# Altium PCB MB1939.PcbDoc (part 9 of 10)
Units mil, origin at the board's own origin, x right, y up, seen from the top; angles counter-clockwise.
Board outline 5910.64 x 4335.93 mil, 6 copper layers (Top Layer, l2_GND, L3_SIG, L4_VCC, L5_GND, Bottom Layer), stack 58.424 mil thick; 635 components, 489 nets, 2289 pads, 1388 vias.
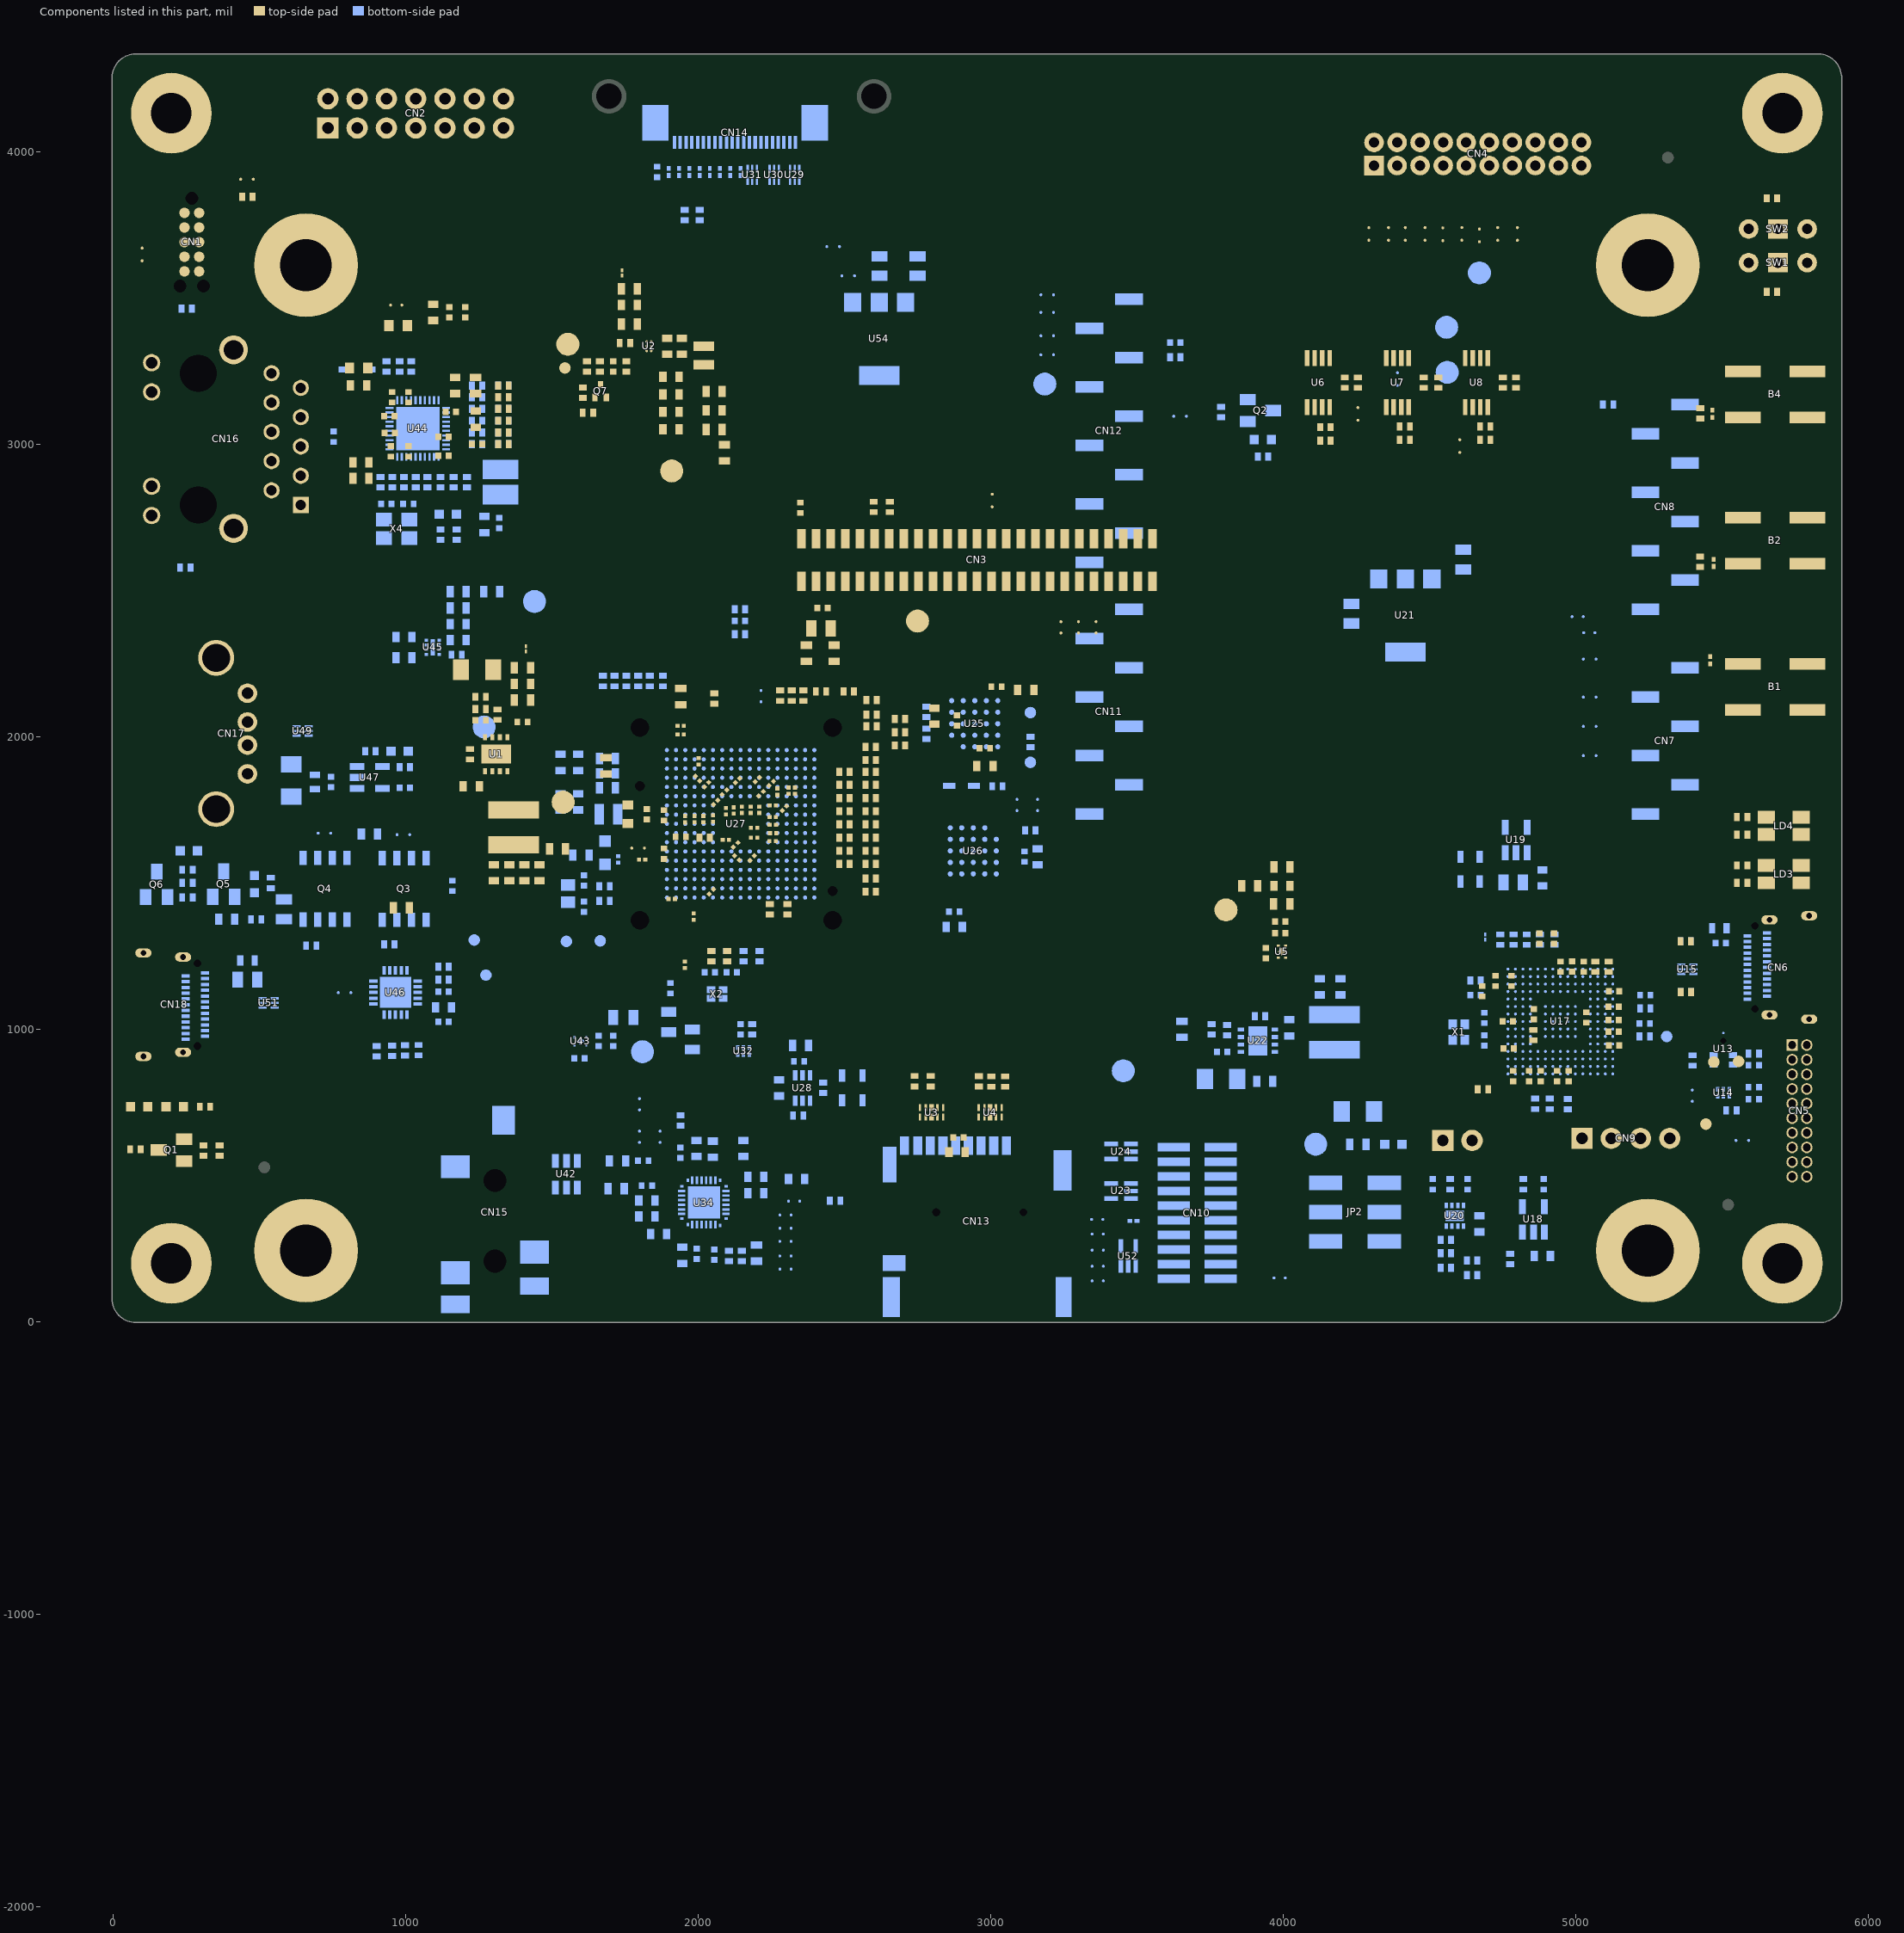
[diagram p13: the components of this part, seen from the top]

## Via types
v1: diameter 20, hole 10, Top Layer to Bottom Layer, tented both sides, 1072 vias
v2: diameter 16, hole 8, Top Layer to Bottom Layer, tented both sides, 316 vias

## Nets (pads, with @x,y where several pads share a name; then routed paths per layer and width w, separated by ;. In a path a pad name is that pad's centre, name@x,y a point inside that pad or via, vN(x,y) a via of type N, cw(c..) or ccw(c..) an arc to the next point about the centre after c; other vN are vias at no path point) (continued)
pads on no net: CN1.7 CN1.11 CN1.12 CN1.13 CN3.41 CN3.42 CN3.44 CN3.46 CN3.48 CN5.3 CN5.7 CN5.8 CN5.9 CN5.11 CN5.13 CN5.14 CN5.15 CN5.16 CN5.17 CN5.18 CN6.0 CN6.A2 CN6.A3 CN6.A8 CN6.A10 CN6.A11 CN6.B2 CN6.B3 CN6.B8 CN6.B10 CN6.B11 CN10.7 CN13.NPTH1 CN13.NPTH2 CN15.5 CN15.7 CN15.MT1 CN15.MT2 CN16.17 CN16.18 CN18.0 CN18.A2 CN18.A3 CN18.A8 CN18.A10 CN18.A11 CN18.B2 CN18.B3 CN18.B8 CN18.B10 CN18.B11 U3.4 U3.5 U3.6 U3.7 U13.6 U17.A1 U17.A2 U17.A3 U17.A4 U17.A5 U17.A8 U17.A9 U17.A11 U17.A12 U17.A13 U17.B1 U17.B2 U17.B3 U17.B4 U17.B5 U17.B6 U17.B7 U17.B8 U17.B9 U17.B10 U17.B11 U17.B12 U17.B13 U17.B14 U17.B15 U17.C2 U17.C3 U17.C12 U17.C13 U17.C14 U17.C15 U17.D1 U17.D2 U17.D3 U17.D11 U17.D13 U17.D14 U17.E1 U17.E2 U17.E3 U17.E4 U17.E12 U17.E13 U17.E14 U17.E15 U17.F1 U17.F4 U17.F14 U17.G4 U17.G14 U17.G15 U17.H2 U17.H3 U17.H4 U17.H14 U17.J3 U17.J4 U17.K1 U17.K2 U17.K3 U17.K12 U17.K13 U17.K14 U17.K15 U17.L1 U17.L12 U17.L13 U17.L14 U17.L15 U17.M2 U17.M3 U17.M4 U17.M7 U17.M12 U17.M13 U17.M14 U17.M15 U17.N2 U17.N4 U17.N6 U17.N7 U17.N11 U17.N13 U17.N14 U17.N15 U17.P2 U17.P4 U17.P5 U17.P6 U17.P7 U17.P8 U17.P9 U17.P10 U17.P11 U17.P12 U17.P13 U17.P14 U17.P15 U17.R2 U17.R3 U17.R6 U17.R7 U17.R8 U17.R9 U17.R10 U17.R11 U17.R12 U17.R13 U19.4 U25.A2 U25.A3 U25.B1 U25.B5 U27.NPTH1 U27.NPTH2 U27.NPTH3 U27.NPTH4 U27.NPTH5 U27.NPTH6 U28.4 U34.16 U34.17 U34.18 U34.25 U34.26

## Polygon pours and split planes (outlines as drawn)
GND on Top Layer "TOP-No Net" (solid, pour order 598): 17 vertices, not listed, extent 1736.9,2998.2 1972.9,3322.8
3V3_STLK on Top Layer "TOP-3V3_STLK" (solid, pour order 248): 62 vertices, not listed, extent 4720,100 5220,885
VDD1V8 on Top Layer "TOP-No Net" (solid, pour order 526): 1519,1692 1604,1692 1667,1629 1667,1571 1643,1547 1537,1547 1517,1567 1517,1639 1511,1645 1511,1679 1512,1680 1512,1685
VDDIO on Top Layer "TOP-VDDIO" (solid, pour order 190): 3844,1350 3699,1350 3680,1369 3680,1520 3700,1540 3855,1540 3869.98,1525.02 3869.98,1515.7 3838.82,1515.7 3838.82,1464.3 3869.98,1464.3 3869.98,1406.71 3870.01,1376.01
VDDCORE on Top Layer "TOP-VDDCORE 1" (solid, pour order 194): 2110,2965 2120,2955 2120,2915.04 2051.96,2847 1867,2847 1850,2864 1850,2950.98 1864.02,2965
VDDCORE on Top Layer "TOP-VDDCORE" (solid, pour order 196): 41 vertices, not listed, extent 1607.2,1915 1745,2091.8
VDD_HEXASPI_M on Top Layer "TOP-VDD_HEXASPI_M" (solid, pour order 198): 3235,1825 3245,1815 3245,1434 3112,1301 2925,1301 2910,1316 2910,1350 2919.49,1359.48 3034.53,1359.48 3035.04,1360 3042,1360 3135,1453 3135,1805 3155,1825 3235,1825
VDD_ETH on Top Layer "TOP-VDD_ETH" (solid, pour order 200): 166 vertices, not listed, extent 740,3225 960,3500
VDD3V3 on Top Layer "TOP-VDD3V3" (solid, pour order 202): 76 vertices, not listed, extent 975,3460 1040,3575
NetL3_1 on Top Layer "TOP-NETL3_1" (solid, pour order 208): 45 vertices, not listed, extent 1255,1715 1480,1860
NetC184_1 on Top Layer "TOP-NETC127_1" (solid, pour order 212): 864,1351 740,1475 740,1625 750,1635 1157,1635 1167,1625 1167,1510.47 1155.53,1499 999.58,1499 963,1462.42 963,1364 950,1351
NetC82_2 on Top Layer "TOP-NETC115_1" (solid, pour order 216): 21 vertices, not listed, extent 2430.02,2300 2515,2492.14
I_SENS_VDDIO_P on Top Layer "TOP-I_SENS_VDDIO_P" (solid, pour order 218): 29 vertices, not listed, extent 4000,1285 4075,1580
NetC21_2 on Top Layer "TOP-NETC50_2" (solid, pour order 222): 21 vertices, not listed, extent 1245,1540 1504,1665
NetC29_2 on Top Layer "TOP-NETC16_2" (solid, pour order 228): 39 vertices, not listed, extent 1725,1740 1896.79,1800
GND on Top Layer "TOP-GND 2" (solid, pour order 234): 50 vertices, not listed, extent 3900,1269.79 3979.98,1384.98
GND on Top Layer "TOP-GND 1" (solid, pour order 236): 1255,1420 1241.02,1433.98 1241.02,1516.02 1244.98,1519.98 1261.46,1519.98 1308.54,1519.98 1321.46,1519.98 1368.54,1519.98 1478.02,1519.98 1487,1511 1487,1429 1478,1420
GND on Top Layer "TOP-GND" (solid, pour order 238): 33 vertices, not listed, extent 1060,3460 1235,3552
5V on Top Layer "TOP-5V 3" (solid, pour order 240): 46 vertices, not listed, extent 1570,3370 1753.43,3550.5
5V on Top Layer "TOP-5V" (solid, pour order 246): 19 vertices, not listed, extent 1410,2085 1500,2255
3V3_DVDD_GMII on Top Layer "TOP-3V3_DVDD_GMII" (solid, pour order 250): 85 vertices, not listed, extent 995.37,3370 1265,3440
3V3_AVDD_GMII on Top Layer "TOP-3V3_AVDD_GMII" (solid, pour order 252): 81 vertices, not listed, extent 855,3165 1030,3290
1V05_AVDD_GMII on Top Layer "TOP-1V05_AVDD_GMII" (solid, pour order 254): 70 vertices, not listed, extent 854.91,2835 1045,3135
I_SENS_INT_VDDCORE_N on Top Layer "TOP-I_SENS_INT_VDDCORE_N" (solid, pour order 258): 1659.6,1815.4 1645,1830 1645,1890 1650,1895 1659.3,1895 1659.3,1853.82 1710.7,1853.82 1710.7,1895 1765,1895 1776.2,1883.8 1776.2,1833.9 1757.7,1815.4
I_SENS_VDDIO_N on Top Layer "TOP-I_SENS_VDDIO_N" (solid, pour order 260): 50 vertices, not listed, extent 3890,1405 3985,1600
NetC82_1 on Top Layer "TOP-NETC115_2" (solid, pour order 214): 26 vertices, not listed, extent 2280,2295 2410,2595
VBUS1 on Top Layer "TOP-VBUS1" (solid, pour order 206): 1027,1346 1002.01,1370.99 1002.01,1454.01 1026,1478 1129,1478 1143,1464 1143,1370 1119,1346
NetC137_2 on Top Layer "TOP-No Net" (solid, pour order 464): 4061,1007 3914,1007 3802,895 3802,763 3813,752 3900,752 3917,769 3917,892 3965,940 4056.31,940 4071,954.69 4071,1000
GND on Top Layer "TOP-No Net" (solid, pour order 470): 1219,2294 1208,2305 1140.25,2305 1130,2294.75 1130,2151 1139,2142 1206,2142 1219,2155
5V on Top Layer "TOP-No Net" (solid, pour order 466): 17 vertices, not listed, extent 3881,517 4338,1292
I_SENS_INT_N on Top Layer "TOP-No Net" (solid, pour order 468): 1265,2281 1356,2281 1386,2251 1386,2099 1395,2090 1395,1986 1387,1978 1347.89,1978 1342.55,1983.34 1342.55,2148.45 1311,2180 1261,2180 1254,2187 1254,2270
VDD_MIC on Top Layer "TOP-No Net" (solid, pour order 476): 5435,1019 5825,1019 5852,992 5852,475 5802,425 5630,425 5327,728 5327,918 5388,979
I_SENS_EXT_VDDCORE_P on Top Layer "TOP-No Net" (solid, pour order 588): 2060,3300 1990,3300 1955,3265 1925,3265 1918.6,3258.6 1918.6,3011.4 1934,2996 2021,2996 2040,3015 2040,3230 2050,3240 2060,3240 2074,3254 2074,3286
I_SENS_EXT_VDDCORE_N on Top Layer "TOP-No Net" (solid, pour order 586): 2068.81,3200 2145,3200 2160,3185 2160,2990 2145,2975 2065,2975 2055,2985 2055,3186.19
I_SENS_EXT_N on Top Layer "TOP-No Net" (solid, pour order 594): 1784.7,3570 1940,3570 1998.1,3511.9 1998.1,3371 1982,3354.9 1849.4,3354.9 1832.3,3354.9 1822.2,3365 1791,3365 1778.18,3377.82 1778.18,3563.48
VDDA1V8 on L3_SIG "TOP-No Net" (solid, pour order 488): 20 vertices, not listed, extent 1915,1760 2331,2228
5V_STLK on L3_SIG "L3_SIG-5V_STLK" (solid, pour order 280): 321 vertices, not listed, extent 4370,149.99 5000,515
5V_STLK on L3_SIG "L3_SIG-5V_STLK 1" (solid, pour order 278): 502 vertices, not listed, extent 4370,150 4980,515
VDDIO_SD on L3_SIG "TOP-No Net" (solid, pour order 500): 3044.4,987 3070,961.4 3070,855 3060,845 2270,845 2235.7,879.3 2075.7,879.3 2040,915 2040,955 2072,987
VBUS_STLK on L3_SIG "L3_SIG-VBUS_STLK" (solid, pour order 272): 29 vertices, not listed, extent 4645,365 4976,475
VBUS_STLK on L3_SIG "L3_SIG-VBUS_STLK 1" (solid, pour order 270): 32 vertices, not listed, extent 4645,390 4955,475
3V3_AVDD_GMII on L3_SIG "L3_SIG-3V3_AVDD_GMII" (solid, pour order 478): 960,3210 960,2920 950,2910 875,2910 865,2920 865,3205 880,3220 950,3220 960,3210
NetL7_2 on L3_SIG "TOP-No Net" (solid, pour order 498): 1794,1728 2094,1728 2108,1714 2108,1680 2104,1676 1808,1676 1784,1700 1784,1718
5V_USB_SNK on L3_SIG "TOP-No Net" (solid, pour order 264): 36 vertices, not listed, extent 817.7,25 4475,1720
VBUS1 on L3_SIG "L3_SIG-No Net" (solid, pour order 544): 295,910 515,910 525,920 545,940 545,1190 545,1395 535,1405 310,1405 275,1370 240,1335 240,950 280,910
VBUS_STLK on L3_SIG "L3_SIG-VBUS_STLK 3" (solid, pour order 266): 179 vertices, not listed, extent 5425,1120 5640,1415
3V3_STLK on L3_SIG "L3_SIG-No Net" (solid, pour order 558): 5241.98,876.98 5241.98,1501.98 5255,1515 5261.56,1515 5835,1515 5875,1555 5875,2065.83 5735,2205.83 4655.83,2205.83 4460,2010 4460,835 4490,805 5170,805
VDD1V8 on Bottom Layer "TOP-No Net" (solid, pour order 490): 17 vertices, not listed, extent 1512,1604.17 1804,1692
5V_STLK on Bottom Layer "TOP-No Net" (solid, pour order 584): 4605,190 4590,205 4590,325 4600,335 4642.44,335 4657.44,320 4754,320 4760,314 4760,250 4745.46,235.46 4650.46,235.46 4645,230 4645,195 4640,190
NetC126_2 on Bottom Layer "BOTTOM-NETC159_2" (solid, pour order 324): 4770,1630 4770,1535.58 4770,1468.44 4770,1460 4750,1440 4580,1440 4560,1460 4560,1530 4575,1545 4690,1545 4700,1555 4700,1630 4710,1640 4760,1640
GND on Bottom Layer "GND_L06_P556" (solid, remove dead copper, pour order 556): 4300,815 4360,815 4370,805 4370,660 4360,650 4290,650 4280,660 4280,795
VBUS_STLK on Bottom Layer "L3_SIG-No Net" (solid, pour order 554): 21 vertices, not listed, extent 5415,1260 5560,1420
VBUS1 on Bottom Layer "BOTTOM-VBUS1" (solid, pour order 314): 30 vertices, not listed, extent 378.2,1125 535.55,1345
VDDA1V8_AON on Bottom Layer "TOP-No Net" (solid, pour order 524): 19 vertices, not listed, extent 1755,856 1940,1108
VDDA1V8 on Bottom Layer "TOP-No Net" (solid, pour order 522): 1310,2538 1341,2538 1365,2514 1484,2514 1497,2501 1497,2402 1479,2384 1334,2384 1304,2414 1304,2531 1306,2533
5V_USB_SNK on Bottom Layer "TOP-No Net" (solid, pour order 502): 4273.75,418.75 4456.25,418.75 4475,400 4475,330 4465,320 4276.25,320 4265,331.25 4265,410
NetC184_1 on Bottom Layer "TOP-No Net" (solid, pour order 456): 810,1713 865,1713 874,1704 874,1436 857,1419 743,1419 731,1431 731,1621 740,1630 790,1630 796,1636 796,1698
GND on Bottom Layer "TOP-No Net" (solid, pour order 436): 4646.31,401.31 4773.69,401.31 4782,393 4782,347 4775,340 4650,340 4635,355 4635,390
I_SENS_VDDA1V8_N on Bottom Layer "BOTTOM-I_SENS_VDDA1V8_N" (solid, pour order 284): 28 vertices, not listed, extent 1192.91,2363.35 1290,2535
VDDIO_SD on Bottom Layer "BOTTOM-VDDIO_SD" (solid, pour order 288): 2040,955 2050,965 2110,965 2120,955 2120,920 2115,915 2055,915 2040,930 2040,955
VDDA1V8 on Bottom Layer "BOTTOM-VDDA1V8" (solid, pour order 292): 208 vertices, not listed, extent 3050,1700 3200,1760
VDD_OCTOSPI_M on Bottom Layer "BOTTOM-VDD_OCTOSPI_M" (solid, pour order 296): 81 vertices, not listed, extent 3060,1775 3125,1900
VDD_HEXASPI_M on Bottom Layer "BOTTOM-VDD_HEXASPI_M" (solid, pour order 302): 91 vertices, not listed, extent 3145.02,1770 3235,1825
VDD3V3 on Bottom Layer "BOTTOM-VDD3V3 1" (solid, pour order 304): 3430,880 3415,895 3415,970 3430,985 3664.3,985 3678,985 3690.55,972.45 3690.55,906.55 3664,880
VDD3V3 on Bottom Layer "BOTTOM-VDD3V3" (solid, pour order 306): 18 vertices, not listed, extent 1005,2305 1084.98,2445
VBUS_STLK on Bottom Layer "BOTTOM-VBUS_STLK" (solid, pour order 310): 4630,415 4600,415 4595,420 4595,460 4603,468 4612.96,468 4612.96,436.22 4647.04,436.22 4647.04,470 4727,470 4739,458 4739,421 4733,415
NetC171_2 on Bottom Layer "BOTTOM-NETC83_2" (solid, pour order 330): 20 vertices, not listed, extent 1615,970 1730,1105
NetC135_2 on Bottom Layer "BOTTOM-NETC54_2" (solid, pour order 334): 49 vertices, not listed, extent 3624,1010 4305,1135
I_SENS_INT_N on Bottom Layer "Bottom Layer-I_SENS_INT_N" (solid, pour order 336): 1255,1855 1255,1785 1250,1780 1220,1780 1215,1785 1215,1865 1355,2005 1355,2085 1365,2095 1390,2095 1395,2090 1395,1995 1255,1855
GND on Bottom Layer "BOTTOM-GND 17" (solid, pour order 338): 62 vertices, not listed, extent 1500,1370 1650,1565
GND on Bottom Layer "BOTTOM-GND 16" (solid, pour order 340): 29 vertices, not listed, extent 1495,1704 1626,1770
GND on Bottom Layer "BOTTOM-GND 15" (solid, pour order 342): 89 vertices, not listed, extent 845,2635 1080,2815.77
GND on Bottom Layer "BOTTOM-GND 14" (solid, pour order 344): 21 vertices, not listed, extent 1998.52,1065 2160,1175
GND on Bottom Layer "BOTTOM-GND 13" (solid, pour order 346): 35 vertices, not listed, extent 2060.55,1152.59 2103.98,1175
GND on Bottom Layer "BOTTOM-GND 12" (solid, pour order 348): 1489.68,1920.02 1479.5,1930.2 1479.5,1991.1 1488.4,2000 1591.6,2000 1615,1976.6 1615,1958.18 1566.98,1958.18 1566.98,1920.02 1554.04,1920.02 1554.04,1958.18 1506.98,1958.18 1506.98,1920.02 1489.68,1920.02
GND on Bottom Layer "BOTTOM-GND 9" (solid, pour order 354): 480,1130 475,1135 475,1145.72 506.36,1145.72 506.36,1192.78 475,1192.78 475,1201.28 475,1248.74 475,1265 480,1270 540,1270 550,1260 550,1145 535,1130
GND on Bottom Layer "BOTTOM-GND 7" (solid, pour order 358): 4824,114 4820.32,117.68 4820.32,209.69 4820,240 4845,265 4864.98,265 4864.98,251.71 4865.69,251 4864.67,248.54 4838.82,248.54 4838.82,201.46 4874.98,201.46 4874.98,151.71 4875.07,118.07 4871,114
GND on Bottom Layer "BOTTOM-GND 5" (solid, pour order 362): 18 vertices, not listed, extent 4075,1160 4270,1285
GND on Bottom Layer "BOTTOM-GND 4" (solid, pour order 364): 21 vertices, not listed, extent 4520,905 4702.9,1075
GND on Bottom Layer "BOTTOM-GND 2" (solid, pour order 368): 46 vertices, not listed, extent 4800,1415 4965,1516.16
GND on Bottom Layer "BOTTOM-GND 1" (solid, pour order 370): 32 vertices, not listed, extent 4122.5,2435 4675,2760
GND on Bottom Layer "BOTTOM-GND" (solid, pour order 372): 24 vertices, not listed, extent 1605.02,865 1740,950.85
5V on Bottom Layer "BOTTOM-5V" (solid, pour order 378): 45 vertices, not listed, extent 1500,870 1585,995
5V_STLK on Bottom Layer "BOTTOM-5V_STLK 1" (solid, pour order 382): 20 vertices, not listed, extent 4885,150 5000,350
3V3_STLK on Bottom Layer "BOTTOM-3V3_STLK 1" (solid, pour order 386): 41 vertices, not listed, extent 4735.6,123.2 4800.3,208
3V3_STLK on Bottom Layer "BOTTOM-3V3_STLK" (solid, pour order 388): 42 vertices, not listed, extent 4823.56,1535 4960,1630
1V05_GMII on Bottom Layer "BOTTOM-1V05_GMII" (solid, pour order 390): 23 vertices, not listed, extent 1215,2735 1410,2860
I_SENS_INT_VDDCORE_N on Bottom Layer "BOTTOM-I_SENS_INT_VDDCORE_N" (solid, pour order 392): 1736.18,1800 1736.18,1938.98 1740.79,1938.98 1763.29,1916.48 1774,1916.48 1774,1809 1765,1800
VIN on Bottom Layer "BOTTOM-VIN" (solid, pour order 286): 18 vertices, not listed, extent 4480,2365 5305,2605
UCPD_SNK on Bottom Layer "BOTTOM-UCPD_SNK" (solid, pour order 318): 905,1420 890.02,1434.98 890,1690 900,1700 975,1700 980,1695 980,1615.42 952.2,1615.42 952.2,1554.18 990,1554.18 990,1430 980,1420
NetL6_1 on Bottom Layer "BOTTOM-NETL4_1" (solid, pour order 320): 59 vertices, not listed, extent 4005,860 4300,970
5V_VIN on Bottom Layer "BOTTOM-5V_VIN" (solid, pour order 380): 22 vertices, not listed, extent 4130,2200 4530,2600
I_SENS_VDDA1V8_P on Bottom Layer "TOP-No Net" (solid, pour order 438): 1165,2517.64 1122.64,2517.64 1109.29,2504.29 1109.29,2308.14 1112.12,2305.32 1165,2305.32
GND on Bottom Layer "TOP-No Net" (solid, pour order 440): 1195,2351.65 1302.35,2351.65 1317,2337 1317,2260 1302,2245 1195,2245 1185,2255 1185,2303.35 1190,2308.35 1190,2349.68
GND on Bottom Layer "BOTTOM-GND 10" (solid, pour order 352): 41 vertices, not listed, extent 905,2305 980,2445
UCPD_SOURCE1 on Bottom Layer "TOP-No Net" (solid, pour order 442): 705,1715 610,1715 565,1670 565,1470 555,1460 545,1450 545,1425 554.09,1415.91 620.91,1415.91 635,1430 712.41,1430 717.13,1434.72 717.13,1702.87
GND on Bottom Layer "TOP-No Net" (solid, pour order 444): 570,1960 780,1960 795,1945 795,1860 790,1855 716.65,1855 711.65,1850 670,1850 654.25,1865.75 554.25,1865.75 545,1875 545,1935.63 549.37,1940
NetC137_2 on Bottom Layer "TOP-No Net" (solid, pour order 460): 3797,898 3837,898 3852,883 3905,883 3919,869 3919,763 3904,748 3808,748 3797,759 3797,859
5V on Bottom Layer "TOP-No Net" (solid, pour order 462): 3950,880 3992,880 4035,837 4187,837 4245,779 4245,218 4215,188 3971,188 3945,214 3945,871 3944,872
I_SENS_INT_VDDCORE_P on Bottom Layer "TOP-No Net" (solid, pour order 492): 17 vertices, not listed, extent 1466,1686 1680,1947.64
5V_STLK on Bottom Layer "TOP-No Net" (solid, pour order 510): 4289,550 4461,550 4471,540 4471,440 4465,434 4283,434 4274,443 4274,534 4275,535
VBUS_STLK on Bottom Layer "TOP-No Net" (solid, pour order 514): 4870.33,469 4987,469 4996,460 4996,380 4982,366 4873,366 4860,379 4860,459.46
GND on Bottom Layer "TOP-No Net" (solid, pour order 516): 4612,563 4598,549 4598,490 4606,482 4728,482 4738,492 4738,556 4731,563
GND on Bottom Layer "TOP-No Net" (solid, pour order 518): 4872,563 4855,546 4855,491 4867,479 4985,479 4998,492 4998,556 4991,563
VBUS2 on Bottom Layer "BOTTOM-VBUS2" (solid, pour order 312): 32 vertices, not listed, extent 400,1735 860,1925
GND on Bottom Layer "TOP-No Net" (solid, pour order 458): 3760,767 3644,767 3630,781 3630,856 3639,865 3676,865 3705,894 3705,938 3710,943 3779,943 3788,934 3788,888 3771.25,871.25 3771.25,777.25 3768,774
NetC200_2 on Bottom Layer "Top Layer-No Net" (solid, remove dead copper, pour order 536): 25 vertices, not listed, extent 2510,3150 2725,3603.54
5V on Bottom Layer "Top Layer-No Net" (solid, remove dead copper, pour order 538): 22 vertices, not listed, extent 2680,3400 2930,3695
GND on Bottom Layer "Top Layer-No Net" (solid, remove dead copper, pour order 540): 17 vertices, not listed, extent 2420,3365 2560,3545
GND on Bottom Layer "Top Layer-No Net" (solid, remove dead copper, pour order 542): 2565,3625 2795,3625 2800,3625 2810,3635 2815,3640 2815,3660 2815,3730 2805,3740 2575,3740 2555,3720 2555,3630 2560,3625
VDD_CAM on Bottom Layer "Bottom Layer-VDD_CAM" (solid, pour order 564): 2444,3553 2448,3549 2497,3549 2501.22,3553.22 2501.22,3596.22 2507,3602 2527,3602 2534,3609 2534,3717 2521,3730 2484,3730 2473.36,3719.36 2473.36,3657.36 2444,3628
NetL7_2 on Bottom Layer "TOP-No Net" (solid, pour order 496): 17 vertices, not listed, extent 1698,1675 1899,1787
NetC184_1 on Bottom Layer "BOTTOM-NETC127_1 1" (solid, pour order 326): 19 vertices, not listed, extent 1010.02,1425 1190,1635
VDDA1V8 on L4_VCC "L4_VCC-VDDA1V8" (solid, pour order 446): 1077 vertices, not listed, extent 1340,1355 4630,3620
5V on L4_VCC "L3_SIG-No Net" (solid, pour order 560): 1360,1390 1360,1520 1260,1520 1250,1510 1245,1505 1245,1415 1290,1415 1315,1390 1330,1390
5V on L4_VCC "TOP-No Net" (solid, pour order 482): 4160,4120 4733.45,4120 4810,4043.45 4810,3833.05 4786.95,3810 4190,3810 4140,3860
5V on L4_VCC "L4_VCC-5V" (solid, pour order 432): 3445 vertices, not listed, extent 610,825 5305,4120
VDDA18AON on L4_VCC "L4_SIG-NetR148_2" (solid, pour order 550): 25 vertices, not listed, extent 1750,1085 2105,1611.04
VBUS_STLK on L4_VCC "TOP-No Net" (solid, pour order 400): 5885.48,1474.98 5309.15,1474.98 5275.02,1440.85 5275.02,1204.02 4625.02,554.02 4625.02,359.12 4649.14,335 4820,335 5461,976 5884.48,976 5885.48,975
VDDIO_SD on L4_VCC "L4_VCC-VDDIO_SD" (solid, pour order 410): 316 vertices, not listed, extent 1895,825 2197.5,1607.5
VDD_OCTOSPI_M on L4_VCC "L4_VCC-VDD_OCTOSPI_M" (solid, pour order 424): 253 vertices, not listed, extent 2650,1790 3150,2220
VBUS_STLK on L4_VCC "TOP-No Net" (solid, pour order 398): 4804,333 4944,333 5033,422 5033,569 4753.17,569 4625.02,440.85 4625.02,359.12 4649.14,335
3V3_DVDD_GMII on L4_VCC "TOP-No Net" (solid, pour order 450): 1400,3360.86 1330.86,3430 1079.14,3430 884.14,3235 575.44,3235 555,3214.56 555,2695.86 474.14,2615 309.14,2615 295,2600.86 295,2564.14 344.14,2515 1010,2515 1010,2588 1400,2978
VDD3V3 on L4_VCC "TOP-No Net" (solid, pour order 480): 4835,4105 5039.69,4105 5063.98,4080.71 5063.98,3843.98 5050,3830 4850,3830 4830,3850
VBUS1 on L4_VCC "L3_SIG-No Net" (solid, pour order 562): 604.14,1485 1100.86,1485 1135,1450.86 1135,1109.14 1110.86,1085 1025,1085 994.14,1085 939.14,1140 875,1140 464.14,1140 445,1159.14 445,1325.86 604.14,1485
VDDCORE on L4_VCC "L4_VCC-VDDCORE" (solid, pour order 448): 850 vertices, not listed, extent 1635.6,1695.5 2352.5,2980
VDDIO on L4_VCC "L4_VCC-VDDIO" (solid, pour order 402): 2111 vertices, not listed, extent 1822.5,270 5885.48,4310.67
VDDIO on L4_VCC "TOP-No Net" (solid, pour order 520): 1848.9,1678.6 1705.6,1678.6 1693,1666 1693,1578 1714,1557 1754.78,1557 1815.3,1617.52 1849.12,1617.52
VDDA1V8_AON on L4_VCC "L4_SIG-VDDA1V8_AON" (solid, pour order 552): 26 vertices, not listed, extent 1615,825 1885,1605
VDD3V3 on L4_VCC "TOP-No Net" (solid, pour order 484): 65 vertices, not listed, extent 20.04,20.04 5885.48,4310.67
GND on l2_GND "L2_GND-GND 9" (solid, pour order 154): 20.04,20.04 20.04,4310.67 5885.48,4310.67 5885.48,20.04 20.04,20.04
GND on L5_GND "L5_GND-GND" (solid, pour order 396): 20.04,4310.67 5885.48,4310.67 5885.48,20.04 20.04,20.04 20.04,4310.67

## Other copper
Top Layer:
  text "1" at 2716.83,4267.41 h31.5
  text ".Layer_Name" at 1632.47,-1647.68 h118.11
  text ".GTL" at 3274,-1647.68 h118.11
l2_GND:
  pour cut-out: 20.5,75.1 75.8,19.8 19.6,19.8 19.6,75.18
  pour cut-out: 5830.5,20.6 5885.8,75.9 5885.8,19.7 5830.42,19.7
  pour cut-out: 5884.9,4255.98 5829.6,4311.28 5885.8,4311.28 5885.8,4255.9
  pour cut-out: 74.92,4310.2 19.62,4254.9 19.62,4311.1 75,4311.1
  text "2" at 2742.03,4267.41 h31.5
  text ".Layer_Name" at 1717.28,-1663.7 h118.11
  text ".G1" at 3311.28,-1671.7 h118.11
L3_SIG:
  text "3" at 2778.45,4267.41 h31.5
  text ".Layer_Name" at 1693.28,-1638.7 h118.11
  text ".G2" at 3307.28,-1658.7 h118.11
L4_VCC:
  pour cut-out: 76.3,4310.8 20.1,4254.6 20.1,4310.8
  pour cut-out: 20.04,76.24 76.24,20.04 20.04,20.04
  pour cut-out: 5829.4,19.9 5885.6,76.1 5885.6,19.9
  pour cut-out: 5885.6,4254.7 5829.4,4310.9 5885.6,4310.9
  text "4" at 2813.92,4267.41 h31.5
  text ".Layer_Name" at 1686.28,-1632.7 h118.11
  text ".G3" at 3296.28,-1645.7 h118.11
L5_GND:
  pour cut-out: 76.24,4310.67 20.04,4254.47 20.04,4310.67
  pour cut-out: 20.04,76.24 76.24,20.04 20.04,20.04
  pour cut-out: 5829.28,20.04 5885.48,76.24 5885.48,20.04
  pour cut-out: 5885.48,4254.47 5829.28,4310.67 5885.48,4310.67
  text "5" at 2847.7,4267.41 h31.5
  text ".Layer_Name" at 1686.28,-1640.7 h118.11
  text ".G4" at 3308.28,-1653.7 h118.11
Bottom Layer:
  text "6" at 2905.57,4267.41 h31.5
  text ".GBL" at 2832.93,-1648.93 h118.11
  text ".Layer_Name" at 4459.46,-1648.93 h118.11
Multi-Layer:
  pour cut-out: 2704,4321.74 2704,4243 2920.54,4243 2920.54,4321.74

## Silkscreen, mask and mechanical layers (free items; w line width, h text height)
Top Overlay:
  lines w5: 2010,1745 2065,1745 2065,1685 2005,1685 ; 2015,1745 2005,1745 2005,1685 ; 2080,1770 2080,1715 2225,1715 2225,1770 ; 2085,1775 2210,1775 ; 2115,1775 2115,1805 2192,1882 2192,1922 2215,1945 2215,1975 ; 2205,1965 2215,1975 ; 2225,1965 2215,1975 ; 3858,1294 3670,1294 3670,1234 3859,1234 3859,1294 ; 1960,1585 1960,1590 1960,1635 1980,1635 1980,1685 2005,1685 ; 1960,1585 2000,1585 2000,1490 1910,1490 1910,1585 1960,1585 ; 10,785 10,851.42 155,851.42 155,785 10,785 ; 170,785 315,785 315,851.42 170,851.42 170,785 ; 210,3365 210,3431.42 340,3431.42 340,3365 210,3365 ; 1315,3399 1565,3399 1565,3467 1315,3467 1315,3399 ; 1387,1844 1610,1844 1610,1904 1387,1904 1387,1844 ; 1792,2735 1792,2795 2075,2795 2075,2735 1792,2735 ; 2090,1975 2090,2085 2230,2085 2308.6,2085 2308.6,1975 2306.5,1975 2090,1975 ; 3425,2805 3545,2805 3545,2844.72 3545,2853.68 3545,2865 3425,2865 3425,2805 ; 5100,4075 5340,4075 5340,4141.42 5273.58,4141.42 5100,4141.42 5100,4075 ; 5605,1970 5775,1970 5775,2009.72 5775,2018.68 5775,2035 5605,2035 5605,1970 ; 5605,2455 5794.03,2455 5794.03,2520 5605,2520 5605,2455 ; 5625,2955 5794.03,2955 5794.03,3020 5625,3020 5625,2955 ; 5685,3425 5885,3425 5885,3441.6 5885,3474.81 5885,3491.42 5818.58,3491.42 5685,3491.42 5685,3425 ; 5685,3876.79 5685,3943.21 5818.58,3943.21 5885,3943.21 5885,3926.6 5885,3893.4 5885,3876.79 5685,3876.79 ; 5835,615 5895,615 5895,735 5855.28,735 5846.32,735 5835,735 5835,615
  text "N" at 1405,4180 h60
  text "STMOD+" at 5110,4090 h60
  text "P" at 1410,4050 h60
  text "GND" at 1050,3895 h60 r90
  text "BOOT0" at 5700,3891.79 h60
  text "INT_IN" at 955,3850 h60 r90
  text "VDDIO" at 1240,3850 h60 r90
  text "EXT_IN" at 740,3835 h60 r90
  text "L" at 5503.1,3793 h60
  text "H" at 5844.7,3790.1 h60
  text "VDDA1V8" at 1345,3775 h60 r90
  text "INT VCORE" at 1150,3725 h60 r90
  text "EXT VCORE" at 870,3715 h60 r90
  text "L" at 5503.9,3525.6 h60
  text "H" at 5845.5,3522.7 h60
  text "BOOT1" at 5700,3440 h60
  text "PWR_ON" at 1325,3417 h60
  text "TAG" at 220,3380 h60
  text "TAMP" at 5635,2965 h60
  text "LCD" at 3435,2815 h60
  text "VDDCORE" at 1802,2745 h60
  text "USER1" at 5615,2470 h60
  text "MCO1" at 2817,2320 h60
  text "NRST" at 5615,1985 h60
  text "VDD1V8" at 1394,1854 h60
  text "J" at 325,1830 h700 r90
  text "VDDIO" at 3681,1244 h60
  text "LED1" at 20,800 h60
  text "LED2" at 180,800 h60
  text "MIC" at 5885,625 h60 r90
  text ".Layer_Name" at 1632.47,-1647.68 h118.11
  text ".GTO" at 3274,-1647.68 h118.11
Bottom Overlay:
  lines w5: 2050,4234.66 2050,4260 2050,4285 ; 2050,4235 2300,4235 ; 2050,4285.34 2300,4285.34 ; 2300,4234.83 2300,4247.41 2300,4272.59 2300,4285.17 ; 2370,420 2385,420 2405,440 ; 2390,440 2405,440 ; 2405,425 2405,440 ; 3400,275 3310,275 3310,185 3310,155 3310,-5 3530,-5 3530,270 ; 4633.3,374.7 4639,380.4 4639,353.7 4642.35,350.35 ; 10,1640 300,1640 300,1703.75 10,1703.75 10,1640 ; 270,805 420,805 420,860 270,860 270,848.75 270,816.25 270,805 ; 280,2348.75 435,2348.75 435,2403.75 280,2403.75 280,2392.5 280,2360 280,2348.75 ; 445,2495 445,2560 750,2560 750,2495 595,2495 445,2495 ; 1015,230 1080,230 1080,580 1015,580 1015,385 1015,230 ; 1045,1905 1045,1927.5 1045,1960 1045,1968.75 1395,1968.75 1395,1905 1045,1905 ; 1051,2118 1334,2118 1334,2181.75 1051,2181.75 1051,2173 1051,2140.5 1051,2118 ; 1070,990 1070,1250 1190,1250 1190,1195 1190,1125 1350,1125 1350,875 1200,875 1200,990 1070,990 ; 1437,2520 1437,2538.5 1437,2571 1437,2579.75 1710,2579.75 1710,2520 1437,2520 ; 1859.7,837.6 1859.7,894.8 2022,894.8 2022,837.6 1909.6,837.6 1859.7,837.6 ; 2480,115 2480,370 2491.25,370 2523.75,370 2540,370 2540,115 2480,115 ; 3298,966 3298,983.25 3298,1021 3527,1021 3527,966 3387,966 3298,966 ; 3630,660 3685,660 3825,660 3825,715 3630,715 3630,660 ; 5500,1510 5720,1510 5875,1510 5875,1575 5500,1575 5500,1510
  lines w6: 310,1545 300,1555 ; 310,1565 300,1555 ; 340,1620 340,1555 300,1555
  text "CAMERA" at 2285,4240 h60
  text "MB1939C" at 5025,4155 h120
  text "E" at 1335,3642 h551.18
  text "K" at 1760,3620 h551.18
  text "I" at 3870,3535 h551.18
  text "MCO2" at 4590,3485 h60
  text "D15" at 3345,3480 h60
  text "D14" at 3345,3425 h60
  text "CSLEEP" at 4815,3325 h60
  text "C" at 2345,3250 h551.18
  text "CSTOP" at 4810,3170 h60
  text "PPS_OUT" at 3130,3135 h60
  text "D13" at 3265,3080 h60
  text "IOREF" at 5575,3000 h60
  text "D12" at 3270,2970 h60
  text "H" at 2870,2955 h551.18
  text "NRST" at 5580,2900 h60
  text "D11" at 3270,2880 h60
  text "S" at 2290,2865 h450
  text "3V3" at 5575,2805 h60
  text "D10" at 3270,2775 h60
  text "5V" at 5570,2705 h60
  text "D9" at 3270,2685 h60
  text "GND" at 5575,2595 h60
  text "D8" at 3270,2565 h60
  text "F" at 2885,2540 h551.18
  text "VDDA1V8" at 1693,2531 h60
  text "G" at 2400,2515 h551.18
  text "ETHERNET" at 740,2510 h60
  text "GND" at 5575,2510 h60
  text "VIN" at 5565,2415 h60
  text "D7" at 3270,2395 h60
  text "USB2" at 425,2360 h60
  text "D6" at 3270,2320 h60
  text "A0" at 5510,2215 h60
  text "D5" at 3270,2210 h60
  text "PWR_ON2" at 1317,2133 h60
  text "D4" at 3275,2120 h60
  text "A1" at 5510,2105 h60
  text "D3" at 3275,2020 h60
  text "A2" at 5515,2015 h60
  text "D2" at 3275,1950 h60
  text "USB2_FAULT" at 1385,1920 h60
  text "A3" at 5515,1910 h60
  text "D1" at 3270,1830 h60
  text "A4" at 5515,1810 h60
  text "D0" at 3335,1765 h60
  text "A5" at 5515,1715 h60
  text "USB1_OCP" at 295,1655 h60
  text "STLINK_V3EC" at 5865,1525 h60
  text "VDD3V3" at 3515,976 h60
  text "VAON" at 2015.8,848.5 h60
  text "USB1" at 410,815 h60
  text "MIPI20" at 3810,670 h60
  text "AUDIO JACK" at 1030,245 h60 r270
  text "1-2:5V_STLK" at 4370,150 h60
  text "SD-CARD" at 2490,125 h60 r270
  text "3-4:5V_USB_SNK" at 4370,90 h60
  text "5-6:5V_VIN" at 4365,25 h60
  text ".GBO" at 2832.93,-1648.93 h118.11
  text ".Layer_Name" at 4459.46,-1648.93 h118.11
Top Paste:
  text ".Layer_Name" at 1632.47,-1647.68 h118.11
  text ".GTP" at 3274,-1647.68 h118.11
Bottom Paste:
  text ".GBP" at 2832.93,-1648.93 h118.11
  text ".Layer_Name" at 4459.46,-1648.93 h118.11
Top Solder:
  text ".Layer_Name" at 1632.47,-1647.68 h118.11
  text ".GTS" at 3274,-1647.68 h118.11
Bottom Solder:
  text ".GBS" at 2832.93,-1648.93 h118.11
  text ".Layer_Name" at 4459.46,-1648.93 h118.11
M1-Board Shape:
  lines w5: -0.1,79.04 ccw(c78.64,79.04) 78.64,0.3 ; 0,72 0,4253.8 ; -0.01,4251.7 cw(c78.73,4251.97) 78.73,4330.71 ; 76.91,4330.71 5826.8,4330.71 ; 78.64,0 5833.81,0 ccw(c5833.81,71.52) 5905.33,71.52 ; 5826.51,4330.64 cw(c5826.77,4251.9) 5905.51,4251.9 5905.51,69.7
M2-Board Dimensions:
  text ".Layer_Name" at 1632.47,-1647.68 h118.11
  text ".GM2" at 3274,-1647.68 h118.11
M14-Top Assembly:
  text ".Layer_Name" at 1632.47,-1647.68 h118.11
  text ".GM14" at 3274,-1647.68 h118.11
M15-Bottom Assembly:
  text ".GM15" at 2832.93,-1648.93 h118.11
  text ".Layer_Name" at 4459.46,-1648.93 h118.11
Drill Drawing:
  drawing of 1182 lines, arcs and shapes, not listed
  text "4" at 6780.7,8171.7 h75
  text "4" at 6780.7,8171.7 h75
  text "LAYER STUCK-UP" at 6980.7,8171.7 h75
  text "LAYER STUCK-UP" at 6980.7,8171.7 h75
  text "SOLDERMASK & SILKSCREEN" at 8740.7,7931.7 h60
  text "SOLDERMASK & SILKSCREEN" at 8740.7,7931.7 h60
  text "TOP     (0.5 oz cu+planted)" at 8740.7,7811.7 h60
  text "TOP     (0.5 oz cu+planted)" at 8740.7,7811.7 h60
  text "PREPREG  3.9 mil" at 7420.7,7646.7 h60
  text "PREPREG  3.9 mil" at 7420.7,7646.7 h60
  text "5" at 91,7545 h100
  text "5" at 91,7545 h100
  text "IMPEDANCE TABLE" at 401,7525 h100
  text "IMPEDANCE TABLE" at 401,7525 h100
  text "LAYER 2 (1 oz)" at 8740.7,7511.7 h60
  text "LAYER 2 (1 oz)" at 8740.7,7511.7 h60
  text "CORE     4  mil" at 7420.7,7411.7 h60
  text "CORE     4  mil" at 7420.7,7411.7 h60
  text "LAYER 3 (1 oz)" at 8740.7,7311.7 h60
  text "LAYER 3 (1 oz)" at 8740.7,7311.7 h60
  text "63 mil" at 6548.7,7239.2 h75
  text "63 mil" at 6548.7,7239.2 h75
  text "LAYER" at 326,7231 h75
  text "LAYER" at 326,7231 h75
  text "TOLERANCE" at 4076,7231 h75
  text "TOLERANCE" at 4076,7231 h75
  text "TRACE" at 1076,7221 h75
  text "TRACE" at 1076,7221 h75
  text "SPACEING" at 1626,7221 h75
  text "SPACEING" at 1626,7221 h75
  text "IMPEDANCE" at 2376,7221 h75
  text "IMPEDANCE" at 2376,7221 h75
  text "IMPEDANCE" at 3276,7221 h75
  text "IMPEDANCE" at 3276,7221 h75
  text "PREPREG  ** mil" at 7420.7,7146.7 h60
  text "PREPREG  ** mil" at 7420.7,7146.7 h60
  text "+/-10%" at 6590.7,7131.7 h50
  text "+/-10%" at 6590.7,7131.7 h50
  text "(mil)" at 1126,7131 h50
  text "(mil)" at 1126,7131 h50
  text "(Single end)" at 2426,7131 h50
  text "(Single end)" at 2426,7131 h50
  text "(mil)" at 1726,7121 h50
  text "(mil)" at 1726,7121 h50
  text "(Differential)" at 3276,7121 h50
  text "(Differential)" at 3276,7121 h50
  text "LAYER 4 (1 oz)" at 8740.7,7011.7 h60
  text "LAYER 4 (1 oz)" at 8740.7,7011.7 h60
  text "1,6" at 321,6985 h75
  text "1,6" at 321,6985 h75
  text "5.0" at 1121,6975 h75
  text "5.0" at 1121,6975 h75
  text "N/A" at 1776,6921 h75
  text "N/A" at 1776,6921 h75
  text "CORE     4  mil" at 7420.7,6911.7 h60
  text "CORE     4  mil" at 7420.7,6911.7 h60
  text "55 OHM" at 2426,6911 h75
  text "55 OHM" at 2426,6911 h75
  text "N/A" at 3426,6911 h75
  text "N/A" at 3426,6911 h75
  text "+/-10%" at 4176,6911 h75
  text "+/-10%" at 4176,6911 h75
  text "4.0" at 1111,6855 h75
  text "4.0" at 1111,6855 h75
  text "3" at 321,6845 h75
  text "LAYER 5 (1 oz)" at 8740.7,6811.7 h60
  text "LAYER 5 (1 oz)" at 8740.7,6811.7 h60
  text "N/A" at 2531,6675 h75
  text "90 OHM" at 3341,6665 h75
  text "+/-10%" at 4176,6661 h75
  text "+/-10%" at 4176,6661 h75
  text "8.9" at 1771,6654 h75
  text "PREPREG  3.9 mil" at 7420.7,6646.7 h60
  text "PREPREG  3.9 mil" at 7420.7,6646.7 h60
  text "1,6" at 300,6645 h75
  text "6.1" at 1112,6631 h75
  text "BOTTOM  (0.5 oz cu+planted)" at 8740.7,6511.7 h60
  text "BOTTOM  (0.5 oz cu+planted)" at 8740.7,6511.7 h60
  text "9.9" at 1762,6421 h75
  text "100 OHM" at 3335,6419 h75
  text "+/-10%" at 4182,6417 h75
  text "6" at 307,6412 h75
  text "5.1" at 1103,6400 h75
  text "N/A" at 2536,6396 h75
  text "SOLDERMASK & SILKSCREEN" at 8740.7,6391.7 h60
  text "SOLDERMASK & SILKSCREEN" at 8740.7,6391.7 h60
  text "6 LAYER STACKING" at 7360.7,6211.7 h75
  text "6 LAYER STACKING" at 7360.7,6211.7 h75
  text "PCB SPECIFICATIONS :" at 6610.86,5747.21 h118.11
  text "PCB : TYPE 3" at 12417.62,5740.43 h118.11
  text "A.   MATERIAL :" at 6610.86,5589.73 h118.11
  text "FR-4" at 8126.61,5589.73 h118.11
  text "TG-170" at 8776.22,5589.73 h118.11
  text "X  TG-150" at 9494.72,5589.73 h118.11
  text "TG-140" at 10124.64,5589.73 h118.11
  text "ASPECT-RATIO, AXE Z :" at 12417.62,5523.89 h118.11
  text "B.   MATERIAL FAMILY :" at 6610.86,5471.62 h118.11
  text "N/A" at 8126.61,5471.62 h118.11
  text "C.   SOLDERMASK COLOR :" at 6610.86,5353.51 h118.11
  text "GREEN" at 8126.61,5353.51 h118.11
  text "WHITE" at 8776.22,5353.51 h118.11
  text "RED" at 9494.72,5353.51 h118.11
  text "BLACK" at 10124.64,5353.51 h118.11
  text "X  Blue ink PANTONE 2955" at 10784.03,5352 h118.11
  text "6:1 to 8:1 / LEVEL \"B\"" at 12418.36,5258.24 h118.11
  text "D.   SILKSCREEN COLOR :" at 6610.86,5235.4 h118.11
  text "X  WHITE" at 8126.61,5235.4 h118.11
  text "YELLOW" at 8776.22,5235.4 h118.11
  text "BLACK" at 9494.72,5235.4 h118.11
  text "Blue ink PANTONE 2955" at 10124.64,5235.4 h118.11
  text "E.   SURFACE FINISH :" at 6610.86,5117.29 h118.11
  text "X  ENIG" at 8126.61,5117.29 h118.11
  text "IMMERSION SILVER" at 8776.22,5117.29 h118.11
  text "IMMERSION TIN" at 10124.64,5117.29 h118.11
  text "MINIMUM PARAMETERS" at 12419.42,5037.73 h118.11
  text "HASL" at 8126.61,4999.18 h118.11
  text "HASL (PB-FREE)" at 8776.22,4999.18 h118.11
  text "GOLDEN FINGER" at 10124.64,4999.18 h118.11
  text "F.   IMPEDANCE CONTROL :" at 6610.86,4881.07 h118.11
  text "NO" at 8126.61,4881.07 h118.11
  text "X   YES  (SEE IMPEDANCE TABLE FOR DETAIL INFORMATION)" at 8776.22,4881.07 h118.11
  text "DEFAULT" at 12419.42,4821.19 h118.11
  text "G.   THROUGH VIA :" at 6610.86,4762.96 h118.11
  text "PLUG THE VIAS WHICH ARE COVERED WITH SOLDERMASK ONE OR TWO SIDE." at 8126.61,4762.96 h118.11
  text "PLUG MATERIAL :" at 8126.61,4644.85 h118.11
  text "X  SOLDERMASK" at 9130.55,4644.85 h118.11
  text "NON-CONDUCTIVE EPOXY." at 10124.64,4644.85 h118.11
  text "TRACKS : 0.127mm           / GAPS : 0.1274mm" at 12419.42,4594.82 h118.11
  text "H.   STACK-UP :" at 6610.86,4526.74 h118.11
  text "SEE LAYER STACK-UP SEQUENCE FOR OVERALL THICKNESS." at 8126.61,4526.74 h118.11
  text "Symbol" at 6500.3,3913.64 h72
  text "Count" at 7006.18,3913.64 h72
  text "Hole Size" at 7646,3913.64 h72
  text "Plated" at 8795.67,3913.64 h72
  text "Hole Type" at 9301.54,3913.64 h72
  text "Drill Layer Pair" at 10035.35,3913.64 h72
  text "Via/Pad" at 11534.9,3913.64 h72
  text "Pad Shape" at 12124.74,3913.64 h72
  text "Template" at 12870.54,3913.64 h72
  text "Description" at 14410.08,3913.64 h72
  text "Hole Tolerance (+)" at 15263.84,3913.64 h72
  text "Hole Tolerance (-)" at 16597.45,3913.64 h72
  text "1" at 7006.18,3763.64 h60
  text "19.69mil (0.500mm)" at 7646,3763.64 h60
  text "NPTH" at 8795.67,3763.64 h60
  text "Round" at 9301.54,3763.64 h60
  text "Top Layer - Bottom Layer" at 10035.35,3763.64 h60
  text "Pad" at 11534.9,3763.64 h60
  text "Rounded" at 12124.74,3763.64 h60
  text "c0hn50m5" at 12870.54,3763.64 h60
  text "C" at 6471.21,3753.65 h66.67
  text "1" at 7006.18,3613.64 h60
  text "27.56mil (0.700mm)" at 7646,3613.64 h60
  text "NPTH" at 8795.67,3613.64 h60
  text "Round" at 9301.54,3613.64 h60
  text "Top Layer - Bottom Layer" at 10035.35,3613.64 h60
  text "Pad" at 11534.9,3613.64 h60
  text "Rounded" at 12124.74,3613.64 h60
  text "c0hn70m5" at 12870.54,3613.64 h60
  text "M" at 6471.21,3603.65 h66.67
  text "2" at 7006.18,3463.64 h60
  text "25.59mil (0.650mm)" at 7646,3463.64 h60
  text "NPTH" at 8795.67,3463.64 h60
  text "Slot" at 9301.54,3463.64 h60
  text "Top Layer - Bottom Layer" at 10035.35,3463.64 h60
  text "Pad" at 11534.9,3463.64 h60
  text "Rounded" at 12124.74,3463.64 h60
  text "c0hn65_95m5" at 12870.54,3463.64 h60
  text "U" at 6471.21,3453.65 h66.67
  text "2" at 7006.18,3313.64 h60
  text "33.47mil (0.850mm)" at 7646,3313.64 h60
  text "NPTH" at 8795.67,3313.64 h60
  text "Round" at 9301.54,3313.64 h60
  text "Top Layer - Bottom Layer" at 10035.35,3313.64 h60
  text "Pad" at 11534.9,3313.64 h60
  text "Rounded" at 12124.74,3313.64 h60
  text "c0hn85m5" at 12870.54,3313.64 h60
  text "2" at 7006.18,3163.64 h60
  text "66.93mil (1.700mm)" at 7646,3163.64 h60
  text "PTH" at 8795.67,3163.64 h60
  text "Round" at 9301.54,3163.64 h60
  text "Top Layer - Bottom Layer" at 10035.35,3163.64 h60
  text "Pad" at 11534.9,3163.64 h60
  text "Rounded" at 12124.74,3163.64 h60
  text "c250h170m255" at 12870.54,3163.64 h60
  text "J" at 6471.21,3153.65 h66.67
  text "2" at 7006.18,3013.64 h60
  text "78.74mil (2.000mm)" at 7646,3013.64 h60
  text "NPTH" at 8795.67,3013.64 h60
  text "Round" at 9301.54,3013.64 h60
  text "Top Layer - Bottom Layer" at 10035.35,3013.64 h60
  text "Pad" at 11534.9,3013.64 h60
  text "Rounded" at 12124.74,3013.64 h60
  text "c50hn200m60" at 12870.54,3013.64 h60
  text "K" at 6471.21,3003.65 h66.67
  text "2" at 7006.18,2863.64 h60
  text "86.61mil (2.200mm)" at 7646,2863.64 h60
  text "PTH" at 8795.67,2863.64 h60
  text "Round" at 9301.54,2863.64 h60
  text "Top Layer - Bottom Layer" at 10035.35,2863.64 h60
  text "Pad" at 11534.9,2863.64 h60
  text "Rounded" at 12124.74,2863.64 h60
  text "c300h220m305p0" at 12870.54,2863.64 h60
  text "R" at 6471.21,2853.65 h66.67
  text "2" at 7006.18,2713.64 h60
  text "94.49mil (2.400mm)" at 7646,2713.64 h60
  text "PTH" at 8795.67,2713.64 h60
  text "Round" at 9301.54,2713.64 h60
  text "Top Layer - Bottom Layer" at 10035.35,2713.64 h60
  text "Pad" at 11534.9,2713.64 h60
  text "Rounded" at 12124.74,2713.64 h60
  text "c310h240m320" at 12870.54,2713.64 h60
  text "2" at 7006.18,2563.64 h60
  text "125.98mil (3.200mm)" at 7646,2563.64 h60
  text "NPTH" at 8795.67,2563.64 h60
  text "Round" at 9301.54,2563.64 h60
  text "Top Layer - Bottom Layer" at 10035.35,2563.64 h60
  text "Pad" at 11534.9,2563.64 h60
  text "Rounded" at 12124.74,2563.64 h60
  text "c100hn320m110" at 12870.54,2563.64 h60
  text "G" at 6471.21,2553.65 h66.67
  text "3" at 7006.18,2413.64 h60
  text "25.59mil (0.650mm)" at 7646,2413.64 h60
  text "NPTH" at 8795.67,2413.64 h60
  text "Round" at 9301.54,2413.64 h60
  text "Top Layer - Bottom Layer" at 10035.35,2413.64 h60
  text "Pad" at 11534.9,2413.64 h60
  text "Rounded" at 12124.74,2413.64 h60
  text "c0hn65m5" at 12870.54,2413.64 h60
  text "P" at 6471.21,2403.65 h66.67
  text "3" at 7006.18,2263.64 h60
  text "43.31mil (1.100mm)" at 7646,2263.64 h60
  text "NPTH" at 8795.67,2263.64 h60
  text "Round" at 9301.54,2263.64 h60
  text "Top Layer - Bottom Layer" at 10035.35,2263.64 h60
  text "Pad" at 11534.9,2263.64 h60
  text "Rounded" at 12124.74,2263.64 h60
  text "c0hn110m5" at 12870.54,2263.64 h60
  text "F" at 6471.21,2253.65 h66.67
  text "4" at 7006.18,2113.64 h60
  text "63.39mil (1.610mm)" at 7646,2113.64 h60
  text "NPTH" at 8795.67,2113.64 h60
  text "Round" at 9301.54,2113.64 h60
  text "Top Layer - Bottom Layer" at 10035.35,2113.64 h60
  text "Pad" at 11534.9,2113.64 h60
  text "Rounded" at 12124.74,2113.64 h60
  text "c0hn161m5" at 12870.54,2113.64 h60
  text "4" at 7006.18,1963.64 h60
  text "137.79mil (3.500mm)" at 7646,1963.64 h60
  text "PTH" at 8795.67,1963.64 h60
  text "Round" at 9301.54,1963.64 h60
  text "Top Layer - Bottom Layer" at 10035.35,1963.64 h60
  text "Pad" at 11534.9,1963.64 h60
  text "Rounded" at 12124.74,1963.64 h60
  text "c700h350m705" at 12870.54,1963.64 h60
  text "4" at 7006.18,1813.64 h60
  text "177.17mil (4.500mm)" at 7646,1813.64 h60
  text "PTH" at 8795.67,1813.64 h60
  text "Round" at 9301.54,1813.64 h60
  text "Top Layer - Bottom Layer" at 10035.35,1813.64 h60
  text "Pad" at 11534.9,1813.64 h60
  text "Rounded" at 12124.74,1813.64 h60
  text "c900h450m905" at 12870.54,1813.64 h60
  text "8" at 7006.18,1663.64 h60
  text "19.69mil (0.500mm)" at 7646,1663.64 h60
  text "PTH" at 8795.67,1663.64 h60
  text "Slot" at 9301.54,1663.64 h60
  text "Top Layer - Bottom Layer" at 10035.35,1663.64 h60
  text "Pad" at 11534.9,1663.64 h60
  text "Rounded" at 12124.74,1663.64 h60
  text "r140_80h50_110r100m145_85" at 12870.54,1663.64 h60
  text "V" at 6471.21,1653.65 h66.67
  text "20" at 7006.18,1513.64 h60
  text "27.56mil (0.700mm)" at 7646,1513.64 h60
  text "PTH" at 8795.67,1513.64 h60
  text "Round" at 9301.54,1513.64 h60
  text "Top Layer - Bottom Layer" at 10035.35,1513.64 h60
  text "Pad" at 11534.9,1513.64 h60
  text "Rounded" at 12124.74,1513.64 h60
  text "(Mixed)" at 12870.54,1513.64 h60
  text "Q" at 6471.21,1503.65 h66.67
  text "28" at 7006.18,1363.64 h60
  text "39.37mil (1.000mm)" at 7646,1363.64 h60
  text "PTH" at 8795.67,1363.64 h60
  text "Round" at 9301.54,1363.64 h60
  text "Top Layer - Bottom Layer" at 10035.35,1363.64 h60
  text "Pad" at 11534.9,1363.64 h60
  text "Rounded" at 12124.74,1363.64 h60
  text "(Mixed)" at 12870.54,1363.64 h60
  text "36" at 7006.18,1213.64 h60
  text "35.43mil (0.900mm)" at 7646,1213.64 h60
  text "PTH" at 8795.67,1213.64 h60
  text "Round" at 9301.54,1213.64 h60
  text "Top Layer - Bottom Layer" at 10035.35,1213.64 h60
  text "Pad" at 11534.9,1213.64 h60
  text "(Mixed)" at 12124.74,1213.64 h60
  text "(Mixed)" at 12870.54,1213.64 h60
  text "316" at 7006.18,1063.64 h60
  text "8.00mil (0.203mm)" at 7646,1063.64 h60
  text "PTH" at 8795.67,1063.64 h60
  text "Round" at 9301.54,1063.64 h60
  text "Top Layer - Bottom Layer" at 10035.35,1063.64 h60
  text "Via" at 11534.9,1063.64 h60
  text "Rounded" at 12124.74,1063.64 h60
  text "v41h20m0mx0" at 12870.54,1063.64 h60
  text "E" at 6471.21,1053.65 h66.67
  text "1072" at 7006.18,913.64 h60
  text "10.00mil (0.254mm)" at 7646,913.64 h60
  text "PTH" at 8795.67,913.64 h60
  text "Round" at 9301.54,913.64 h60
  text "Top Layer - Bottom Layer" at 10035.35,913.64 h60
  text "Via" at 11534.9,913.64 h60
  text "Rounded" at 12124.74,913.64 h60
  text "v51h25m0mx0" at 12870.54,913.64 h60
  text "D" at 6471.21,903.65 h66.67
  text "1514 Total" at 7006.18,763.64 h60
  text "Slot definitions :" at 6500.3,618.67 h60
  text "Routed Path Length" at 7532.99,618.67 h60
  text "= Calculated from tool start centre position to tool end centre position." at 8635.66,618.67 h60
  text "Hole Length" at 7532.99,518.69 h60
  text "= Routed Path Length + Tool Size = Slot length as defined in the PCB layout" at 8225.79,518.69 h60
  text ".Layer_Name" at 1632.47,-1647.68 h118.11
  text ".DRL" at 3274,-1647.68 h118.11
M20-Top Title Box:
  circle w10: c4703.5,-1912.27 r51.18
  region: 4133.5,-1955.31 3710.04,-1955.31 3749.15,-1857.16 4058.5,-1857.16 4076.17,-1827.27 4163.12,-1927.6
  region: 4684.81,-1627.37 4073.5,-1627.37 4046.17,-1697.27 3998.5,-1745.49 3943.5,-1672.27 3943.5,-1607.27 3988.5,-1552.27 4045.04,-1537.37 4684.81,-1537.37
  lines w10: 3749.15,-1857.16 4095.28,-1857.16 3974.57,-1717.88 cw(c4045.58,-1641.35) 4055.04,-1537.37 4715.04,-1537.37 4685.04,-1627.37 ; 3879.61,-1527.64 cw(c3975.12,-1565.85) 3984.44,-1463.4 ; 3881.15,-1526.36 3710.04,-1955.31 4470.77,-1955.31 ccw(c4480.56,-1847.65) 4580.92,-1887.8 ; 3949.64,-1681.28 4163.12,-1927.6 ; 3959.64,-1681.28 4168.5,-1922.27 ; 3959.64,-1671.28 4168.5,-1912.27 ; 3963.5,-1627.37 4475.04,-1627.37 ; 3964.64,-1666.28 4173.5,-1907.27 ; 3969.64,-1661.28 4178.5,-1902.27 ; 3974.64,-1656.28 4183.5,-1897.27 ; 3979.64,-1651.28 4188.5,-1892.27 ; 3981.8,-1574.41 4190.66,-1815.4 ; 3984.49,-1463.4 4750.22,-1463.4 4580.96,-1887.7 ; 3984.64,-1646.28 4191.36,-1884.79 ; 3984.64,-1636.28 4193.5,-1877.27 ; 3984.64,-1626.28 4193.5,-1867.27 ; 3984.64,-1591.28 4193.5,-1832.27 ; 3989.64,-1621.28 4198.5,-1862.27 ; 3989.64,-1606.28 4198.5,-1847.27 ; 4043.65,-1857.69 ccw(c4047.78,-1836.62) 4059.5,-1818.62 ; 4086.42,-1626.85 ccw(c4085.4,-1649.18) 4072.4,-1667.37 4165.5,-1774.8 cw(c4094.49,-1851.33) 4123.33,-1951.67 ; 4333.72,-1947.27 4447.47,-1617.37 ; 4342.47,-1945.31 4455.44,-1617.72 ; 4347.47,-1945.31 4460.44,-1617.72 ; 4357.47,-1945.31 4470.44,-1617.72 ; 4367.47,-1945.31 4480.44,-1617.72 ; 4377.47,-1945.31 4490.44,-1617.72 ; 4387.47,-1945.31 4500.44,-1617.72 ; 4397.47,-1945.31 4510.44,-1617.72 ; 4407.47,-1945.31 4520.44,-1617.72 ; 4417.47,-1945.31 4530.44,-1617.72 ; 4425.69,-1947.27 4539.44,-1617.37 ; 4539.44,-1627.37 4684.81,-1627.37 ; 4658.5,-1627.27 4688.5,-1537.27 ; 4665.04,-1627.37 4695.04,-1537.37 ; 4675.04,-1627.37 4705.04,-1537.37
  lines w11.81: 1278.13,-1911.45 3640.34,-1911.45 ; 1278.13,-1714.6 3640.34,-1714.6 ; 1278.13,-1517.75 3640.34,-1517.75 ; 2852.94,-2108.3 2852.94,-1517.75 ; 3640.34,-2108.3 3640.34,-1320.9 ; 4333.72,-1947.27 4425.69,-1947.27 ; 1278.13,-2108.3 4821.44,-2108.3 4821.44,-1320.9 1278.13,-1320.9 1278.15,-2108.3
  text "Project: '.Board_Name'" at 1317.51,-1447.52 h118.11
  text "Layer:" at 1317.52,-1647.68 h118.11
  text "Gerber:" at 2891.87,-1647.68 h118.11
  text "Variant: '.VariantName'" at 1317.51,-1844.53 h118.11
  text "Ref: '.Board_Reference'" at 2896.87,-1844.53 h118.11
  text "R" at 4683.5,-1942.27 h60
  text "Date: '.Board_Document_Date'" at 1317.51,-2041.38 h118.11
  text "Rev: '.Board_PCB_Revision'" at 2894.63,-2041.38 h118.11
M21-Bottom Title Box:
  circle w10: c1403.44,-1912.27 r51.18
  region: 1422.13,-1627.37 2033.44,-1627.37 2060.78,-1697.27 2108.44,-1745.49 2163.44,-1672.27 2163.44,-1607.27 2118.44,-1552.27 2061.91,-1537.37 1422.13,-1537.37
  region: 1973.44,-1955.31 2396.91,-1955.31 2357.8,-1857.16 2048.44,-1857.16 2030.78,-1827.27 1943.82,-1927.6
  lines w10: 1401.91,-1537.37 1431.91,-1627.37 ; 1411.91,-1537.37 1441.91,-1627.37 ; 1418.44,-1537.27 1448.44,-1627.27 ; 1421.91,-1627.37 1391.91,-1537.37 2051.91,-1537.37 cw(c2061.36,-1641.35) 2132.38,-1717.88 2011.66,-1857.16 2357.8,-1857.16 ; 1422.13,-1627.37 1567.5,-1627.37 ; 1526.02,-1887.8 ccw(c1626.39,-1847.65) 1636.17,-1955.31 2396.91,-1955.31 2225.8,-1526.36 ; 1525.98,-1887.7 1356.72,-1463.4 2122.46,-1463.4 ; 1567.5,-1617.37 1681.26,-1947.27 ; 1576.51,-1617.72 1689.47,-1945.31 ; 1586.51,-1617.72 1699.47,-1945.31 ; 1596.51,-1617.72 1709.47,-1945.31 ; 1606.51,-1617.72 1719.47,-1945.31 ; 1616.51,-1617.72 1729.47,-1945.31 ; 1626.51,-1617.72 1739.47,-1945.31 ; 1631.91,-1627.37 2143.44,-1627.37 ; 1636.51,-1617.72 1749.47,-1945.31 ; 1646.51,-1617.72 1759.47,-1945.31 ; 1651.51,-1617.72 1764.47,-1945.31 ; 1659.47,-1617.37 1773.23,-1947.27 ; 1908.44,-1862.27 2117.3,-1621.28 ; 1908.44,-1847.27 2117.3,-1606.28 ; 1913.44,-1877.27 2122.3,-1636.28 ; 1913.44,-1867.27 2122.3,-1626.28 ; 1913.44,-1832.27 2122.3,-1591.28 ; 1915.59,-1884.79 2122.3,-1646.28 ; 1916.29,-1815.4 2125.15,-1574.41 ; 1918.44,-1892.27 2127.3,-1651.28 ; 1923.44,-1897.27 2132.3,-1656.28 ; 1928.44,-1902.27 2137.3,-1661.28 ; 1933.44,-1907.27 2142.3,-1666.28 ; 1938.44,-1922.27 2147.3,-1681.28 ; 1938.44,-1912.27 2147.3,-1671.28 ; 1943.82,-1927.6 2157.3,-1681.28 ; 1983.61,-1951.67 cw(c2012.46,-1851.33) 1941.44,-1774.8 2034.54,-1667.37 ccw(c2021.54,-1649.18) 2020.52,-1626.85 ; 2047.44,-1818.62 ccw(c2059.16,-1836.62) 2063.3,-1857.69 ; 2122.51,-1463.4 cw(c2131.82,-1565.85) 2227.34,-1527.64
  lines w11.81: 1681.26,-1947.27 1773.23,-1947.27 ; 2459.24,-2108.3 2459.24,-1320.9 ; 2459.24,-1911.45 4821.44,-1911.45 ; 2459.24,-1714.6 4821.44,-1714.6 ; 2459.24,-1517.75 4821.44,-1517.75 ; 3246.64,-2108.3 3246.64,-1517.75 ; 1278.13,-2108.3 1278.13,-1320.9 4821.44,-1320.9 4821.44,-2108.3 1278.13,-2108.3
  text "Project: '.Board_Name'" at 4774.43,-1447.52 h118.11
  text "Gerber:" at 3200.07,-1647.68 h118.11
  text "Layer:" at 4774.42,-1647.68 h118.11
  text "Ref: '.Board_Reference'" at 3200.07,-1844.53 h118.11
  text "Variant: '.VariantName'" at 4774.43,-1844.53 h118.11
  text "R" at 1423.44,-1942.27 h60
  text "Rev: '.Board_PCB_Revision'" at 3202.32,-2041.38 h118.11
  text "Date: '.Board_Document_Date'" at 4774.43,-2041.38 h118.11

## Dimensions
0,4330.71 to 0,0 on M2-Board Dimensions
200,200 to 200,4130.71 on M2-Board Dimensions
659.96,243.35 to 659.96,3611.06 on M2-Board Dimensions
200,4130.71 to 5705.51,4130.71 on M2-Board Dimensions
5245.79,3611.06 to 659.96,3611.06 on M2-Board Dimensions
